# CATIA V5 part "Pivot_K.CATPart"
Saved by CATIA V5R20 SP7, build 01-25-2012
Part number: Pivot_K
Bounding box of the stored display mesh (mm): x -152.5 to -147.5, y 27.5 to 32.5, z -6 to 6
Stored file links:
  D:\IFMA\COURS\2A\projet balance IAO\catia\Pivot_K.CATPart
  D:\IFMA\COURS\2A\projet balance IAO\catia\Ass_projet_balance.CATProduct
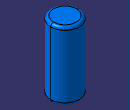
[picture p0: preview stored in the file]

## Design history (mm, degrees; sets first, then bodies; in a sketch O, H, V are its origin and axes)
Set1
  Plane1 "Plan_plateau_gauche": linked copy from another document
  Point1 "Point.K": linked copy from another document
Body1 (main body)
  Sketch1 on Plane1, origin (0, 0, 0), H (1, 0, 0), V (0, 1, 0)
    circle A1 centre (-150, 30) radius 2.5
    point P1 (-150, 30)
    reference projected point E1 (-150, 30) from Point1
    radius A1 = 2.5
    coincidence: P1 E1
  Pad1: profile Sketch1, direction (0, 0, 1), length 6, mirrored extent
  Fillet1: radius 0.5, on edge [face of Pad1 from Sketch1.A1 | end face of Pad1]; edge [start face of Pad1 | face of Pad1 from Sketch1.A1]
